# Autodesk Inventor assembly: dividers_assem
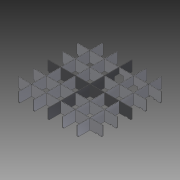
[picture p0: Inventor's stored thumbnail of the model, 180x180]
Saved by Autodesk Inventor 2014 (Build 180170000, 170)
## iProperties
Created: 2014-05
Part Number: dividers_assem
Document SubType Name: Assembly
Designer: t_emanb
Author: t_emanb
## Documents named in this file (8)
- C:\Users\t_emanb\Documents\Disco Panel Table\Version 1\dividers_assem.iam
- C:\Users\t_emanb\Documents\Disco Panel Table\Version 1\dividers_led.ipt
- C:\Users\t_emanb\Documents\Disco Panel Table\Version 1\dividers.ipt
- C:\Users\t_emanb\Documents\Disco Panel Table\Version 1\dividers_led_mid.ipt
- C:\Users\t_emanb\Documents\Disco Panel Table\Version 1\dividers_mid.ipt
- C:\Users\t_emanb\Documents\Disco Panel Table\Version 1\dividers_ard.ipt
- C:\Users\t_emanb\Documents\Disco Panel Table\Version 1\dividers_elec.ipt
- C:\Users\t_emanb\Documents\Disco Panel Table\Version 1\dividers_end.ipt
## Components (10 placed, 7 different names)
1. dividers_elec:1 — Flush:4, Flush:29, Mate:12
2. dividers_led:2 — Flush:4, Mate:7, Flush:22, Flush:25, Flush:27, Flush:29
3. dividers_led:4 — Flush:1, Flush:5, Mate:9, Flush:24, Flush:25, Flush:27
4. dividers_led:5 — Flush:1, Flush:5, Mate:10, Flush:17
5. dividers:1 — Flush:9, Flush:16, Mate:7, Mate:9, Mate:10, Flush:17, Mate:11, Mate:17
6. dividers:2 — Flush:9, Flush:16, Flush:26, Flush:28, Mate:16
7. dividers_ard:1 — Flush:12, Flush:13, Flush:21, Flush:26, Mate:14
8. dividers_end:1 — Flush:12, Flush:13, Mate:12, Mate:13
9. dividers_led_mid:1 — Mate:11, Flush:23, Flush:24, Mate:13, Mate:14, Mate:15, Mate:16, Mate:17
10. dividers_mid:1 — Flush:21, Flush:22, Flush:23, Flush:28, Mate:15
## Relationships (27: Flush 17, Mate 10)
- Flush:1: dividers_led:4 ↔ dividers_led:5
- Flush:4: dividers_elec:1 ↔ dividers_led:2
- Flush:5: dividers_led:4 ↔ dividers_led:5
- Flush:9: dividers:1 ↔ dividers:2
- Flush:12: dividers_ard:1 ↔ dividers_end:1
- Flush:13: dividers_ard:1 ↔ dividers_end:1
- Flush:16: dividers:1 ↔ dividers:2
- Mate:7: dividers_led:2 ↔ dividers:1
- Mate:9: dividers_led:4 ↔ dividers:1
- Mate:10: dividers_led:5 ↔ dividers:1
- Flush:17: dividers_led:5 ↔ dividers:1
- Mate:11: dividers:1 ↔ dividers_led_mid:1
- Flush:21: dividers_ard:1 ↔ dividers_mid:1
- Flush:22: dividers_led:2 ↔ dividers_mid:1
- Flush:23: dividers_led_mid:1 ↔ dividers_mid:1
- Flush:24: dividers_led:4 ↔ dividers_led_mid:1
- Flush:25: dividers_led:2 ↔ dividers_led:4
- Flush:26: dividers:2 ↔ dividers_ard:1
- Flush:27: dividers_led:2 ↔ dividers_led:4
- Flush:28: dividers:2 ↔ dividers_mid:1
- Flush:29: dividers_elec:1 ↔ dividers_led:2
- Mate:12: dividers_elec:1 ↔ dividers_end:1
- Mate:13: dividers_end:1 ↔ dividers_led_mid:1
- Mate:14: dividers_ard:1 ↔ dividers_led_mid:1
- Mate:15: dividers_led_mid:1 ↔ dividers_mid:1
- Mate:16: dividers:2 ↔ dividers_led_mid:1
- Mate:17: dividers:1 ↔ dividers_led_mid:1
